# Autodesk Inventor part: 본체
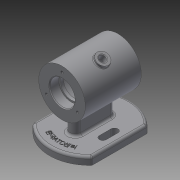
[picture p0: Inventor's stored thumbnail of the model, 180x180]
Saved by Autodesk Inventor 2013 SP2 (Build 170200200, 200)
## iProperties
Created: 2022-02
Part Number: 본체
Material: Generic
Document SubType Name: Modeling
Designer: i
Density: 1 g/cm^3
Author: i
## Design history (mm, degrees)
sketch "스케치1"
  geometry: L1 (-36, 0)-(36, 0); L2 (-36, 0)-(-36, 30); L3 (-36, 30)-(36, 30); L4 (36, 30)-(36, 0); L5 (-36, 16)-(-24, 16); L6 (-24, 16)-(-24, 14); L7 (-24, 14)-(-20, 14); L8 (-20, 14)-(-20, 25); L9 (-20, 25)-(20, 25); L10 (20, 25)-(20, 14); L11 (20, 14)-(24, 14); L12 (24, 14)-(24, 16); L13 (24, 16)-(36, 16); 2 further points
  constraints: 26 end point, 6 perpendicular, 5 parallel, 2 point on line, 1 coincident, 1 collinear, 1 horizontal, 1 midpoint
  dimensions: "d0" = 72 distance of L1.end L1.start; "d2" = 60 diameter of L3 L1; "d3" = 32 diameter of L5 L1; "d4" = 28 diameter of L7 L1; "d5" = 50 diameter of L9 L1; "d6" = 28 diameter of L11 L1; "d7" = 32 diameter of L13 L1; "d8" = 12 distance from line of L6.end L2; "d9" = 12 distance from line of L4 L12.end; "d10" = 40 distance between parallel lines of L10 L8; "d11" = 4 distance from line of L11.end L10
revolve "회전1" sketch "스케치1" stored, may be unused: angle "d12" = 90 deg
fillet "모깎기1" dims "d13" = 0.3
fillet "모깎기2" dims "d14" = 3
chamfer "모따기1" distance "d15" = 1; stored, may be unused: second distance "d16" = 2, angle "d17" = 45 deg
sketch "스케치2"
  geometry: C1 r 30 at (0, 0) reference; 1 further point
  constraints: 1 vertical alignment
  dimensions: "d18" = 23 distance of point (0, 23) C1.centre
hole "구멍1" sketch "스케치2" at (0, 23) diameter "d19" = 3.242; stored, may be unused: countersink angle "d23" = 90 deg, drill point angle "d25" = 118 deg; dims "d20" = 8, "d21" = 4, "d22" = 2, "d24" = 10
sketch "스케치3"
  geometry: L1 (0, 0)-(28.579, 16.5); L2 (0, 0)-(33, 0); C1 r 25 at (0, 0) reference; C2 r 30 at (0, 0) reference; 2 further points
  constraints: 4 end point, 1 coincident, 1 equal length, 1 horizontal
  dimensions: "d29" = 33 distance of L1.start L1.end; "d30" = 30 deg angle of L2 L1
  node "절단 모서리 투영1"
node "작업 평면1"
sketch "스케치4"
  geometry: C1 r 8 at (0, 0); 1 further point
  constraints: 1 centre point, 1 coincident
  dimensions: "d31" = 16 diameter of C1
extrude "돌출1" join sketch "스케치4" stored distance "d32" = 10; taper "d33" = 0 deg
sketch "스케치5"
  geometry: C1 r 8 at (0, 0) reference; C2 r 4 at (0, 0)
  constraints: 1 centre point, 1 coincident
  dimensions: "d34" = 8 diameter of C2
extrude "돌출2" cut sketch "스케치5" stored distance "d35" = 10; taper "d36" = 0 deg
fillet "모깎기3" dims "d37" = 1
node "작업 평면2"
sketch "스케치6"
  geometry: L1 (-35.496, 38)-(35.496, 38); L2 (-35.496, -38)-(35.496, -38); A1 r 52 centre (0, 0) between (-35.496, 38) and (-35.496, -38); A2 r 52 centre (0, 0) between (35.496, -38) and (35.496, 38); 1 further point
  constraints: 4 end point, 4 point on circle, 2 centre point, 1 coincident, 1 horizontal, 1 parallel
  dimensions: "d43" = 76 distance between parallel lines of L2 L1; "d44" = 38 distance from line of L1 point (0, 0); "d45" = 52 radius of A1; "d46" = 52 radius of A2
extrude "돌출3" join sketch "스케치6" distance "d47" = 10; taper "d48" = 0 deg
sketch "스케치7"
  geometry: L1 (19, -7)-(-19, -7); L2 (-19, -7)-(-19, 7); L3 (-19, 7)-(19, 7); L4 (19, 7)-(19, -7); L5 (19, -7)-(-19, 7); L6 (-19, -7)-(19, 7); A1 r 52 centre (0, 0) between (-35.496, 38) and (-35.496, -38) reference; A2 r 7 centre (-19, 0) between (-19, 7) and (-19, -7); A3 r 7 centre (19, 0) between (19, -7) and (19, 7)
  constraints: 12 end point, 4 midpoint, 4 point on circle, 2 centre point, 2 parallel, 1 horizontal, 1 perpendicular
  dimensions: "d49" = 38 distance of L2.end L3.end; "d50" = 14 distance of L1.end L2.end
extrude "돌출4" join sketch "스케치7" stored distance "d51" = 0; taper "d52" = 0 deg
sketch "스케치8"
  geometry: L1 (-7.5, 28.5)-(7.5, 28.5); L2 (7.5, 28.5)-(7.5, 19.5); L3 (7.5, 19.5)-(-7.5, 19.5); L4 (-7.5, 19.5)-(-7.5, 28.5); A1 r 52 centre (0, 0) between (35.496, -38) and (35.496, 38) reference; A2 r 4.5 centre (7.5, 24) between (7.5, 19.5) and (7.5, 28.5); A3 r 4.5 centre (-7.5, 24) between (-7.5, 28.5) and (-7.5, 19.5); 1 further point
  constraints: 8 end point, 4 point on circle, 3 midpoint, 2 centre point, 2 parallel, 1 horizontal, 1 perpendicular, 1 vertical alignment
  dimensions: "d53" = 15 distance of L2.end L3.end; "d54" = 9 distance of L1.end L2.end; "d55" = 24 vertical distance of A2.centre A1.centre
extrude "돌출5" cut sketch "스케치8" stored distance "d56" = 10; taper "d57" = 0 deg
fillet "모깎기4" dims "d58" = 3
fillet "모깎기5" dims "d59" = 3
fillet "모깎기6" dims "d60" = 3
sketch "스케치10"
  geometry: C1 r 42.5 at (0, 0); A1 r 49 centre (0, 0) between (34.293, -35) and (34.293, 35) reference
  constraints: 1 centre point, 1 coincident, 1 other
  dimensions: "d65" = 85 diameter of C1
feature "엠보싱2" sketch "스케치10" dims "d0" = 72, "d2" = 60, "d3" = 32, "d4" = 28, "d5" = 50, "d6" = 28, "d7" = 32, "d8" = 12, "d9" = 12, "d10" = 40, "d11" = 4, "d14" = 3, "d66" = 0.5, "d67" = 0
fillet "모깎기7" dims "d68" = 0.3
node "솔리드1"
pattern_circular "원형 패턴1" dims angle "d27" = 360 deg
mirror "대칭1"
mirror "대칭2"
other parameters: "d38" = -62, "d42" = 104
